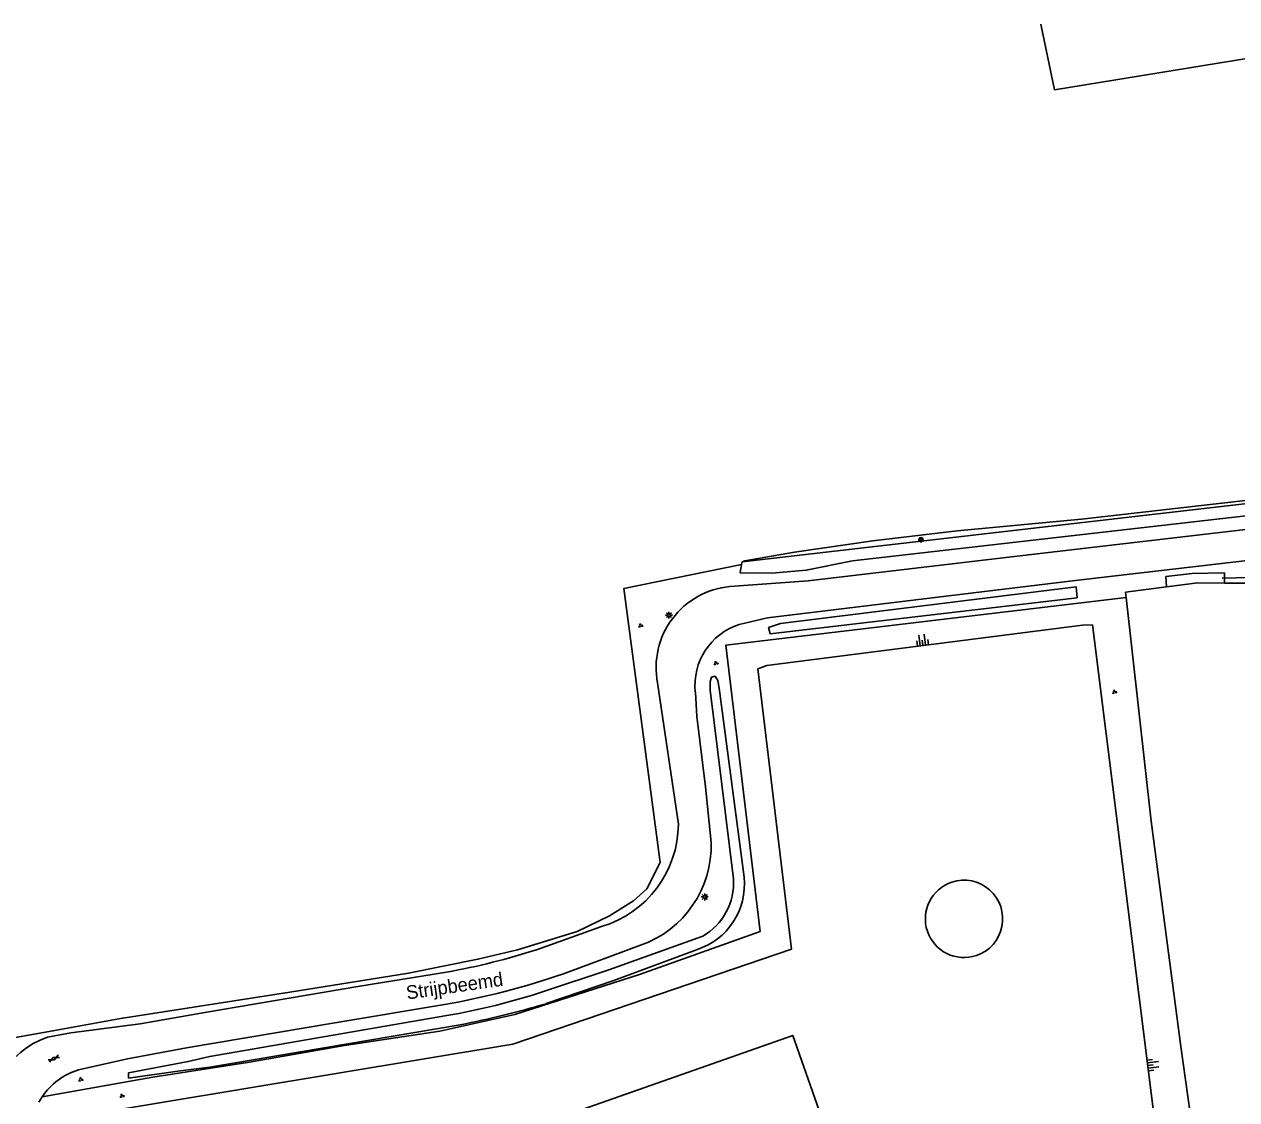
# Model space of a CAD drawing. Extents: x 124000 to 129000, y 395500 to 397503.
# Drawn here: x 126092.4 to 126314, y 397303.4 to 397500 of the extents above; entities that cross this region are included whole.
import ezdxf

# ---------------------------------------------------------------- set-up
doc = ezdxf.new("R2010")
doc.units = 0
for name, color, linetype in [('gg-afsc-lijn draadraster', 7, 'Continuous'), ('gg-anno-openbare ruimte label', 7, 'Continuous'), ('gg-bbg-hoofdgebouw', 7, 'Continuous'), ('gg-bbg-luifel en loopbrug', 7, 'Continuous'), ('gg-knt-bovenkant onderkant talud', 7, 'Continuous'), ('gg-knt-bronhoudergrens', 7, 'Continuous'), ('gg-knt-verharding', 7, 'Continuous'), ('gg-kntw-greppel-droge sloot', 7, 'Continuous'), ('gg-kwrk-duiker nz buis', 7, 'Continuous'), ('gg-kwrk-keermuur', 7, 'Continuous'), ('gt-grn-groengrens', 7, 'Continuous'), ('gt-grn-vlakafsluiter', 7, 'Continuous'), ('gt-symb-boom', 7, 'Continuous'), ('gt-symb-gesloten verharding', 7, 'Continuous'), ('gt-symb-groenvak', 7, 'Continuous'), ('gt-symb-lichtmast', 7, 'Continuous'), ('gt-symb-talud symbool', 7, 'Continuous'), ('gx-grn-maaiveld', 7, 'Continuous')]:
    doc.layers.add(name, color=color, linetype=linetype)

# ---------------------------------------------------------------- blocks, each defined once
blk = doc.blocks.new('gt0-GRVAK')
at = {"layer": 'gt-symb-groenvak'}
for p, q in [((-0.11, 0.19), (-0.23, 0.24)), ((-0.18, 0.15), (0.09, 0.15)), ((-0.09, 0.21), (-0.16, 0.32)), ((-0.05, 0.21), (-0.05, 0.39)), ((0, 0.21), (0.06, 0.32)), ((0.01, 0.19), (0.13, 0.24)), ((0.26, -0.05), (0.2, 0.06)), ((0.3, -0.05), (0.3, 0.13)), ((0.35, -0.05), (0.41, 0.06)), ((-0.25, -0.23), (-0.36, -0.18)), ((-0.32, -0.26), (-0.05, -0.26)), ((-0.23, -0.21), (-0.29, -0.09)), ((-0.18, -0.2), (-0.18, -0.02)), ((-0.14, -0.21), (-0.07, -0.09)), ((-0.12, -0.23), (0, -0.18)), ((0.24, -0.07), (0.12, -0.02)), ((0.17, -0.11), (0.44, -0.11)), ((0.37, -0.07), (0.49, -0.02))]:
    blk.add_line(p, q, dxfattribs=at)
blk = doc.blocks.new('gt0-BOOM')
at = {"layer": 'gt-symb-boom'}
for radius in [0.4, 0.2]:
    blk.add_circle((0, 0), radius, dxfattribs=at)
blk = doc.blocks.new('gt0-TALUD_1')
at = {"layer": 'gt-symb-talud symbool'}
for p, q in [((-1, -1), (-1, 0)), ((-0.5, -2), (-0.5, 0)), ((0, -1), (0, 0)), ((0.5, -2), (0.5, 0)), ((1, -1), (1, 0))]:
    blk.add_line(p, q, dxfattribs=at)
blk = doc.blocks.new('gt0-LMAST')
at = {"layer": 'gt-symb-lichtmast'}
for p, q in [((-0.18, 0.17), (-0.45, 0.44)), ((-0.01, 0.25), (-0.01, 0.62)), ((0.17, 0.17), (0.44, 0.44)), ((-0.26, 0), (-0.63, 0)), ((-0.18, -0.18), (-0.45, -0.45)), ((-0.01, -0.25), (-0.01, -0.63)), ((0.44, -0.45), (0.17, -0.18)), ((0.24, 0), (0.62, 0))]:
    blk.add_line(p, q, dxfattribs=at)
blk.add_circle((-0.01, 0), 0.25, dxfattribs=at)
blk = doc.blocks.new('gt0-GESVH1')
at = {"layer": 'gt-symb-gesloten verharding'}
for p, q in [((-0.99, -0.26), (0.01, 0.24)), ((0.01, -0.26), (-0.99, 0.24)), ((0.01, 0.24), (1.01, -0.26)), ((1.01, 0.24), (0.01, -0.26))]:
    blk.add_line(p, q, dxfattribs=at)

msp = doc.modelspace()

# ---------------------------------------------------------------- linework, layer by layer
at = {"layer": 'gg-afsc-lijn draadraster'}
msp.add_lwpolyline([(126278.2, 397500), (126280.71, 397487.99), (126324.08, 397495.07)], dxfattribs=at)
at = {"layer": 'gg-bbg-hoofdgebouw'}
msp.add_lwpolyline([(126199.06, 397285.08), (126175.29, 397276.71), (126169.53, 397292.94), (126232.87, 397315.18), (126248.92, 397269.36)], dxfattribs=at)
at = {"layer": 'gg-bbg-luifel en loopbrug'}
for start, end in [(108.5695, 288.5592), (288.5592, 108.5695)]:
    msp.add_arc((126264.15, 397336.47), 7.07, start, end, dxfattribs=at)
at = {"layer": 'gg-knt-bovenkant onderkant talud'}
for points in [[(126095.64, 397303.94), (126115.9, 397307.55), (126133.54, 397310.29), (126150.93, 397313.31), (126168.32, 397315.96), (126182.06, 397319.01), (126204.81, 397326.31), (126226.88, 397334.18), (126220.62, 397386.5), (126293.79, 397395.2)], [(126293.79, 397395.2), (126298.38, 397354.34), (126303.79, 397313.16), (126306.32, 397294.88), (126308.42, 397275.79)]]:
    msp.add_lwpolyline(points, dxfattribs=at)
at = {"layer": 'gg-knt-bronhoudergrens'}
msp.add_lwpolyline([(126203.72, 397339.79), (126206.18, 397341.99), (126208.6, 397346.77), (126201.97, 397396.89), (126223.5, 397401.22)], dxfattribs=at)
at = {"layer": 'gg-knt-verharding'}
for p, q in [((126208.15, 397379.61), (126211.94, 397353.78)), ((126197.91, 397335.06), (126186.19, 397330.88)), ((126190.96, 397326.45), (126205.03, 397331.65))]:
    msp.add_line(p, q, dxfattribs=at)
for points in [[(126433.69, 397421.51), (126418, 397419.74), (126379.03, 397415.1), (126321.87, 397408.35), (126272.82, 397402.64), (126235.67, 397398.26), (126221.34, 397397.21)], [(126223.02, 397390.27), (126228.23, 397391.47), (126284, 397398.26), (126340.02, 397404.77), (126395.97, 397411.41), (126437.83, 397416.48)], [(126217.92, 397350.45), (126216.88, 397360.62), (126215.31, 397373.46), (126215.04, 397377.94)], [(126169.58, 397326.75), (126153.32, 397324.09), (126125.38, 397319.35), (126113.56, 397317.28), (126100.91, 397315.66), (126096.63, 397314.85)], [(126102.32, 397308.86), (126111.22, 397310.88), (126122.01, 397312.87), (126149.17, 397317.46), (126169.21, 397320.81)], [(126095.06, 397302.97), (126095.34, 397303.46), (126095.64, 397303.94)]]:
    msp.add_lwpolyline(points, dxfattribs=at)
for centre, radius, start, end in [((126222.73, 397382.42), 14.86, 95.3816, 190.9025), ((126226.67, 397379.16), 11.7, 108.1628, 185.9651), ((126192.2, 397353.95), 19.74, 286.8136, 359.4966), ((126198.61, 397349.87), 19.32, 289.4284, 1.7331), ((126147.89, 397449.25), 124.41, 280.0399, 287.9287), ((126144.48, 397461.11), 142.46, 279.9972, 289.0427), ((126101.53, 397300.33), 15.33, 108.6415, 192.8607), ((126105.74, 397297.21), 12.14, 106.365, 146.3247)]:
    msp.add_arc(centre, radius, start, end, dxfattribs=at)
at = {"layer": 'gg-kntw-greppel-droge sloot'}
for p, q in [((126223.58, 397401.73), (126223.5, 397401.22)), ((126301.17, 397397.16), (126301.02, 397399.07)), ((126172.07, 397317.11), (126126.3, 397309.34))]:
    msp.add_line(p, q, dxfattribs=at)
for points in [[(126223.5, 397401.22), (126223.24, 397399.71), (126229, 397399.65), (126235.3, 397400.21), (126243.75, 397401.89), (126365.26, 397415.8), (126365.02, 397418.09), (126223.58, 397401.73)], [(126301.02, 397399.07), (126305.82, 397399.61), (126311.75, 397399.7), (126311.78, 397397.85)], [(126311.78, 397397.85), (126306.87, 397397.87), (126301.17, 397397.16)], [(126228.73, 397388.6), (126228.43, 397389.72), (126230.62, 397390.47), (126284.65, 397397.15), (126284.8, 397395.16), (126228.73, 397388.6)], [(126222.01, 397343.77), (126217.73, 397378.25), (126217.74, 397379.86), (126217.98, 397380.68), (126218.65, 397380.81), (126219.12, 397380.05), (126219.42, 397378.63), (126223.95, 397344.1)], [(126187.26, 397323.19), (126199.24, 397327.14), (126216.4, 397333.31)], [(126215.25, 397330.84), (126200.17, 397325.2), (126187.76, 397320.98)], [(126126.3, 397309.34), (126120.47, 397308.63), (126111.46, 397307.38), (126111.43, 397308.3), (126122.36, 397310.39), (126126.27, 397311.33), (126169.59, 397318.8)]]:
    msp.add_lwpolyline(points, dxfattribs=at)
for centre, radius, start, end in [((126211.53, 397342.76), 12.49, 287.3201, 6.1594), ((126210.8, 397343.05), 11.23, 299.9404, 3.6577), ((126149.64, 397437.01), 119.88, 279.5792, 288.2887), ((126136.8, 397493.97), 180.35, 281.2769, 286.4138)]:
    msp.add_arc(centre, radius, start, end, dxfattribs=at)
at = {"layer": 'gg-kwrk-duiker nz buis'}
msp.add_line((126311.31, 397398.75), (126320.3, 397398.97), dxfattribs=at)
at = {"layer": 'gg-kwrk-keermuur'}
msp.add_line((126290.12, 397370.3), (126300.77, 397285.52), dxfattribs=at)
for points in [[(126226.47, 397382.19), (126228.11, 397382.79), (126285.8, 397390.17), (126287.62, 397390.19), (126290.12, 397370.3)], [(126098.9, 397299.59), (126100.61, 397300.11), (126181.7, 397313.59), (126232.6, 397330.93), (126226.47, 397382.19)]]:
    msp.add_lwpolyline(points, dxfattribs=at)
at = {"layer": 'gt-grn-groengrens'}
msp.add_line((126319.93, 397397.86), (126311.78, 397397.85), dxfattribs=at)
msp.add_lwpolyline([(126439.16, 397426.99), (126376, 397419.86), (126285.64, 397409.54), (126262.89, 397407.42), (126247.48, 397405.57), (126233.19, 397403.52), (126224.1, 397401.89), (126223.58, 397401.73)], dxfattribs=at)
at = {"layer": 'gt-grn-vlakafsluiter'}
for p, q in [((126301.17, 397397.16), (126293.66, 397396.22)), ((126293.66, 397396.22), (126293.79, 397395.2))]:
    msp.add_line(p, q, dxfattribs=at)
at = {"layer": 'gx-grn-maaiveld'}
msp.add_lwpolyline([(126081.82, 397313.18), (126097.62, 397315.98), (126110.36, 397318.31), (126110.37, 397318.31), (126140.89, 397323.06), (126162.59, 397326.55), (126175.29, 397329.1), (126182.54, 397330.84), (126193.44, 397334.18), (126199.37, 397337.03), (126203.72, 397339.79)], dxfattribs=at)

# ---------------------------------------------------------------- block references
at = {"layer": 'gt-symb-boom'}
msp.add_blockref('gt0-BOOM', (126256.27, 397405.78), dxfattribs=at)
at = {"layer": 'gt-symb-gesloten verharding', "rotation": 26.180521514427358}
msp.add_blockref('gt0-GESVH1', (126097.77, 397310.94), dxfattribs=at)
at = {"layer": 'gt-symb-groenvak'}
for p in [(126205.03, 397390.09), (126218.79, 397383.21), (126291.62, 397377.97), (126102.68, 397307.12), (126110.2, 397304.11)]:
    msp.add_blockref('gt0-GRVAK', p, dxfattribs=at)
at = {"layer": 'gt-symb-lichtmast'}
for p in [(126210.23, 397391.98), (126216.76, 397340.48)]:
    msp.add_blockref('gt0-LMAST', p, dxfattribs=at)
at = {"layer": 'gt-symb-talud symbool'}
for p, xscale, yscale, rotation in [((126256.64, 397386.44), 1.0002239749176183, 1.0002239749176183, -172.64762064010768), ((126297.74, 397309.68), 0.9999864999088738, 0.9999864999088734, 96.77678283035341)]:
    msp.add_blockref('gt0-TALUD_1', p, dxfattribs=dict(at, xscale=xscale, yscale=yscale, rotation=rotation))

# ---------------------------------------------------------------- texts
at = {"layer": 'gg-anno-openbare ruimte label'}
msp.add_text('Strijpbeemd', height=2.5, rotation=8.2, dxfattribs=at).set_placement((126162.37, 397321.72))

doc.saveas('drawing.dxf')
